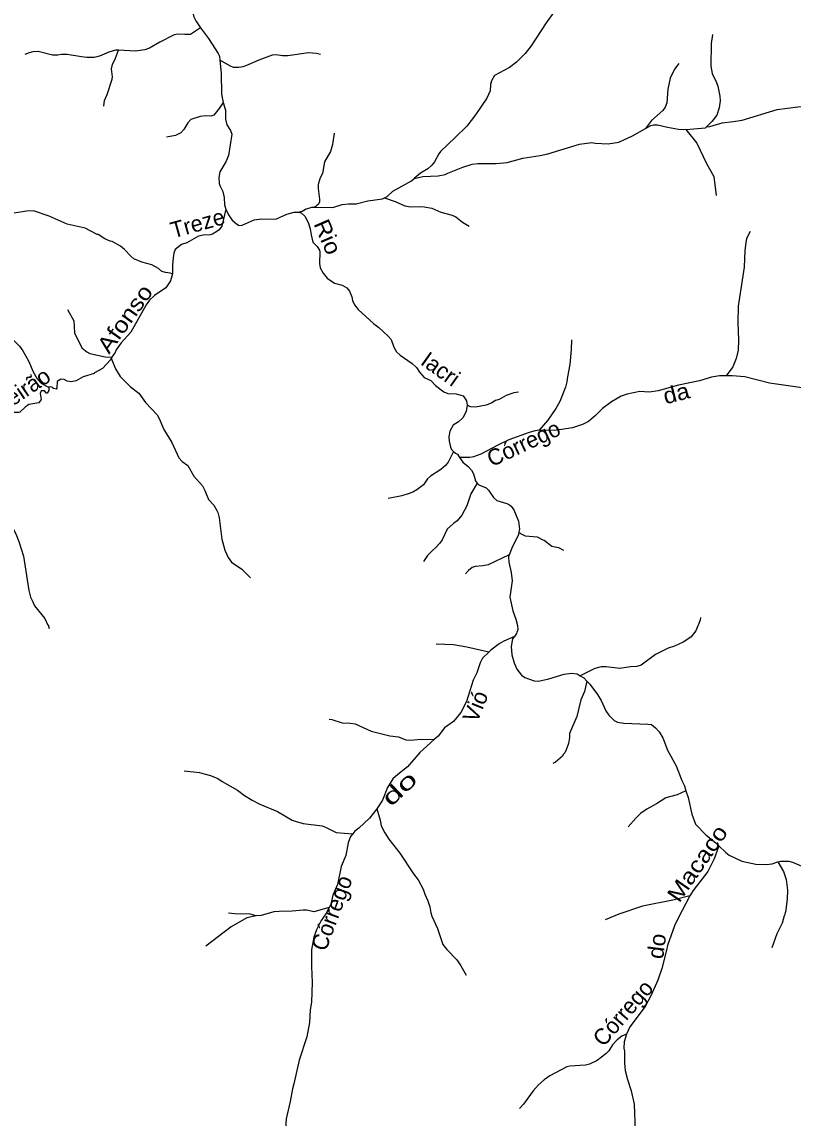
# Model space of a CAD drawing. Extents: x 551.6 to 577.6, y 7567 to 7594.7.
# Drawn here: x 558.55 to 563.33, y 7579.74 to 7586.53 of the extents above; entities that cross this region are included whole.
import ezdxf
from ezdxf.enums import TextEntityAlignment as Align

# ---------------------------------------------------------------- set-up
doc = ezdxf.new("R2010")
doc.units = 0
doc.header["$LTSCALE"] = 0.04
doc.layers.add('61', color=7, linetype='Continuous')
doc.layers.add('7', color=7, linetype='Continuous', lineweight=25)

msp = doc.modelspace()

# ---------------------------------------------------------------- linework, layer by layer
at = {"layer": '7'}
for points in [[(559.5927, 7586.7884), (559.5906, 7586.773), (559.6019, 7586.6313), (559.6188, 7586.5669), (559.6316, 7586.5412), (559.6598, 7586.4975)], [(562.1378, 7586.789), (562.0388, 7586.7271), (561.9632, 7586.6949), (561.9302, 7586.6739), (561.8505, 7586.5959), (561.8022, 7586.5291), (561.7104, 7586.3867), (561.6734, 7586.3392), (561.6195, 7586.2844), (561.5761, 7586.2522), (561.4835, 7586.2032), (561.4642, 7586.1694), (561.4585, 7586.1468), (561.4561, 7586.1066), (561.4352, 7586.0615), (561.3644, 7585.9585), (561.3104, 7585.8885), (561.2388, 7585.8184)], [(559.6598, 7586.4975), (559.5971, 7586.4575), (559.5633, 7586.4559), (559.5182, 7586.4591), (559.4964, 7586.4542), (559.4071, 7586.41), (559.3427, 7586.3722), (559.3138, 7586.3617), (559.2574, 7586.3544), (559.152, 7586.3605)], [(559.6598, 7586.4975), (559.7089, 7586.4317), (559.7701, 7586.3392), (559.7773, 7586.3231), (559.7798, 7586.2986)], [(562.834, 7586.4567), (562.8259, 7586.4011), (562.8243, 7586.2595), (562.8331, 7586.2144), (562.8597, 7586.1581), (562.8669, 7586.1356), (562.8806, 7586.0744), (562.8822, 7586.0454), (562.8758, 7586.002), (562.8613, 7585.9569), (562.8299, 7585.9166), (562.7969, 7585.8836)], [(559.152, 7586.3605), (559.1335, 7586.3601), (559.0908, 7586.348), (559.0337, 7586.3223), (558.9999, 7586.315), (558.9548, 7586.3142), (558.9226, 7586.3174), (558.8325, 7586.3335), (558.7971, 7586.3327), (558.7745, 7586.3279), (558.7424, 7586.3295), (558.6538, 7586.3504), (558.62, 7586.3496), (558.5975, 7586.344), (558.5709, 7586.3335)], [(559.0602, 7586.0124), (559.0651, 7586.047), (559.0803, 7586.084), (559.1117, 7586.179), (559.1134, 7586.1951), (559.1077, 7586.2434), (559.1142, 7586.2708), (559.1335, 7586.3094), (559.152, 7586.3605)], [(560.4043, 7586.3319), (560.3793, 7586.3392), (560.3294, 7586.3424), (560.2007, 7586.3247), (560.1685, 7586.3247), (560.1298, 7586.3303), (560.1041, 7586.3287), (560.0204, 7586.2981), (559.9455, 7586.2635), (559.9222, 7586.2563), (559.8964, 7586.253)], [(559.7798, 7586.2986), (559.7886, 7586.216), (559.7902, 7586.0857), (559.7993, 7586.0346)], [(559.8964, 7586.253), (559.8642, 7586.253), (559.8449, 7586.2603), (559.7798, 7586.2986)], [(562.6255, 7586.2764), (562.5989, 7586.2418), (562.5716, 7586.1855), (562.5571, 7586.1179), (562.5506, 7586.0325), (562.5402, 7586.0068), (562.5257, 7585.9851), (562.4557, 7585.9231), (562.4193, 7585.8736)], [(559.7993, 7586.0346), (559.7749, 7585.9971), (559.7419, 7585.9569), (559.7242, 7585.9504), (559.692, 7585.952), (559.6566, 7585.9472), (559.6003, 7585.9295), (559.5809, 7585.9094), (559.5568, 7585.8668), (559.5383, 7585.8474), (559.5053, 7585.8305), (559.4498, 7585.8201)], [(559.7993, 7586.0346), (559.8143, 7585.9875), (559.8143, 7585.9311), (559.824, 7585.8973), (559.8465, 7585.8619), (559.853, 7585.8378)], [(562.9627, 7585.9166), (563.0191, 7585.9263), (563.2347, 7585.9907), (563.3635, 7586.0084), (563.4504, 7586.0092), (563.5229, 7586.0003), (563.6162, 7585.9714), (563.7039, 7585.9335), (563.7321, 7585.9134), (563.7997, 7585.878), (563.8335, 7585.8563), (563.8842, 7585.8088)], [(562.1064, 7585.7838), (562.1869, 7585.779), (562.2529, 7585.7887), (562.339, 7585.8281), (562.4193, 7585.8736)], [(562.4193, 7585.8736), (562.4525, 7585.8925), (562.4686, 7585.8973), (562.4927, 7585.8965), (562.5555, 7585.8812), (562.6231, 7585.87), (562.6694, 7585.8681)], [(562.6694, 7585.8681), (562.7921, 7585.878), (562.7969, 7585.8836)], [(562.6694, 7585.8681), (562.7382, 7585.7831), (562.7985, 7585.6575), (562.8436, 7585.577), (562.8581, 7585.4587)], [(562.7969, 7585.8836), (562.8179, 7585.886), (562.8951, 7585.9086), (562.9627, 7585.9166)], [(559.853, 7585.8378), (559.8328, 7585.7058), (559.8159, 7585.6672), (559.7805, 7585.606), (559.7741, 7585.5706), (559.7757, 7585.5336), (559.7789, 7585.5207), (559.7982, 7585.4821), (559.8063, 7585.445), (559.8095, 7585.4), (559.8176, 7585.3735)], [(560.4896, 7585.845), (560.4775, 7585.775), (560.4662, 7585.7316), (560.4284, 7585.6672), (560.4163, 7585.5955), (560.401, 7585.5674), (560.3898, 7585.5271), (560.3898, 7585.5014), (560.3986, 7585.4354), (560.397, 7585.4161), (560.3889, 7585.4016), (560.3689, 7585.3865)], [(561.2388, 7585.8184), (561.1471, 7585.7307), (561.1366, 7585.7171), (561.1109, 7585.6672), (561.0948, 7585.6454), (561.069, 7585.6229), (561.0232, 7585.5971), (560.9854, 7585.5634)], [(561.1938, 7585.5963), (561.2871, 7585.6341), (561.3451, 7585.6527), (561.3789, 7585.6575), (561.4932, 7585.6559), (561.5608, 7585.6623), (561.659, 7585.6897), (561.7652, 7585.7058), (561.8135, 7585.717), (562.0098, 7585.7766), (562.0871, 7585.7863), (562.1064, 7585.7838)], [(560.9854, 7585.5634), (561.0376, 7585.5754), (561.1342, 7585.5802), (561.1761, 7585.5891), (561.1938, 7585.5963)], [(560.8011, 7585.444), (560.8163, 7585.4523), (560.8533, 7585.4845), (560.9682, 7585.5485), (560.9854, 7585.5634)], [(560.3689, 7585.3865), (560.4807, 7585.3839), (560.5387, 7585.4032), (560.5773, 7585.4072), (560.6256, 7585.4064), (560.698, 7585.4249), (560.7882, 7585.437), (560.8011, 7585.444)], [(560.8011, 7585.444), (560.8662, 7585.4209), (560.9266, 7585.3943), (560.962, 7585.3871), (561.0215, 7585.3903), (561.0457, 7585.3887), (561.094, 7585.379), (561.1503, 7585.3557), (561.2211, 7585.3364), (561.2421, 7585.3251), (561.2839, 7585.2929), (561.325, 7585.2672)], [(560.2681, 7585.3542), (560.29, 7585.3613), (560.3117, 7585.3742), (560.3503, 7585.3855), (560.3689, 7585.3865)], [(559.4867, 7584.9721), (559.4715, 7584.9774), (559.4425, 7584.9798), (559.42, 7584.9879), (559.3991, 7585.0048), (559.3572, 7585.0281), (559.2952, 7585.045), (559.2462, 7585.0652), (559.2276, 7585.0813), (559.189, 7585.1239), (559.1641, 7585.144), (559.111, 7585.173), (559.0997, 7585.1746), (559.0659, 7585.1891), (559.0256, 7585.2165), (559.0192, 7585.2165), (558.9436, 7585.2559), (558.8325, 7585.28), (558.7222, 7585.3291), (558.624, 7585.3629), (558.5798, 7585.3613), (558.5041, 7585.3484)], [(559.8176, 7585.3735), (559.7918, 7585.2688), (559.7749, 7585.2462), (559.7612, 7585.235), (559.7339, 7585.2189), (559.7194, 7585.2148), (559.6759, 7585.2132), (559.647, 7585.2052), (559.5745, 7585.1641), (559.5423, 7585.1537), (559.5021, 7585.1231), (559.494, 7585.1006), (559.4892, 7585.0716), (559.486, 7585.0265), (559.4867, 7584.9721)], [(559.8176, 7585.3735), (559.8328, 7585.3388), (559.8554, 7585.3058), (559.8819, 7585.2825), (559.8988, 7585.2728), (559.919, 7585.2744), (559.993, 7585.3074), (560.0381, 7585.3138), (560.1186, 7585.3106), (560.1314, 7585.313), (560.1958, 7585.3428), (560.2409, 7585.3549), (560.2681, 7585.3542)], [(560.2681, 7585.3542), (560.2843, 7585.3517), (560.3061, 7585.3292), (560.327, 7585.2905), (560.3407, 7585.2519), (560.3455, 7585.2133), (560.3568, 7585.1682)], [(563.0674, 7585.235), (563.0456, 7585.1907), (563.0408, 7585.165), (563.0351, 7585.1167), (563.0311, 7585.0137), (562.9941, 7584.7722), (562.9909, 7584.6692), (562.9957, 7584.563), (562.9941, 7584.4986), (562.982, 7584.4471), (562.9603, 7584.3956), (562.9199, 7584.3408)], [(560.3568, 7585.1682), (560.3825, 7585.1424), (560.397, 7585.1199), (560.4002, 7585.1086), (560.397, 7585.0362), (560.4018, 7585.0105), (560.4195, 7584.9766), (560.4445, 7584.9452), (560.4904, 7584.9147), (560.5387, 7584.9018), (560.5676, 7584.8849), (560.5837, 7584.864), (560.5982, 7584.8302), (560.6014, 7584.8076), (560.6143, 7584.7795), (560.6376, 7584.7521), (560.7318, 7584.6652), (560.7664, 7584.6402), (560.8243, 7584.5863), (560.8412, 7584.5646), (560.8582, 7584.5179), (560.8759, 7584.4889), (560.8976, 7584.4672), (560.9732, 7584.4157), (560.999, 7584.3908), (561.0175, 7584.3634)], [(559.4867, 7584.9721), (559.4739, 7584.93), (559.4441, 7584.8857), (559.3749, 7584.8382), (559.3427, 7584.8093), (559.3234, 7584.7803), (559.2268, 7584.6113), (559.1673, 7584.5437), (559.1367, 7584.5002), (559.1254, 7584.4753), (559.1222, 7584.4745), (559.1102, 7584.4558), (559.1061, 7584.4495)], [(558.8341, 7584.7521), (558.8743, 7584.6805), (558.8784, 7584.6064), (558.9242, 7584.5139), (558.954, 7584.4881), (558.9725, 7584.4793), (559.0675, 7584.4567), (559.1102, 7584.4558)], [(558.3343, 7584.6724), (558.3738, 7584.6563), (558.4349, 7584.6201), (558.4856, 7584.5759), (558.5363, 7584.5243), (558.5588, 7584.4954), (558.5943, 7584.4278), (558.6192, 7584.3698), (558.6474, 7584.3215), (558.6723, 7584.2942), (558.7037, 7584.2748), (558.7194, 7584.2696)], [(561.9599, 7584.5638), (561.9583, 7584.5034), (561.9495, 7584.4101), (561.935, 7584.3344), (561.9318, 7584.3022), (561.9229, 7584.27), (561.8883, 7584.1815), (561.8634, 7584.138), (561.8126, 7584.0648), (561.7608, 7584.0026)], [(559.1061, 7584.4495), (559.1021, 7584.4382), (559.053, 7584.3859), (559.0031, 7584.3577), (559.0007, 7584.3537), (558.9323, 7584.3336), (558.8888, 7584.3086), (558.8582, 7584.303)], [(559.1061, 7584.4495), (559.1335, 7584.3827), (559.1624, 7584.336), (559.2252, 7584.2708), (559.2783, 7584.233), (559.3194, 7584.1751), (559.391, 7584.0978), (559.4039, 7584.0753), (559.4329, 7584.0077), (559.4811, 7583.9272), (559.5262, 7583.8306), (559.5463, 7583.8081), (559.5809, 7583.7839), (559.618, 7583.7179), (559.6711, 7583.6584), (559.6872, 7583.6294), (559.7097, 7583.5723), (559.7419, 7583.5377), (559.762, 7583.5039), (559.7677, 7583.4926), (559.7757, 7583.4588)], [(561.0175, 7584.3634), (561.0457, 7584.3304), (561.0875, 7584.3119), (561.1173, 7584.2805), (561.168, 7584.241), (561.1938, 7584.2306), (561.2453, 7584.229), (561.2895, 7584.2153), (561.3096, 7584.1847), (561.3136, 7584.1572)], [(558.8582, 7584.303), (558.8325, 7584.3078), (558.8148, 7584.3175), (558.7939, 7584.3191), (558.7761, 7584.3095), (558.7713, 7584.3038), (558.7689, 7584.2636), (558.7641, 7584.2563), (558.7456, 7584.262), (558.7456, 7584.2652), (558.7388, 7584.2703), (558.7269, 7584.2725), (558.7194, 7584.2696)], [(562.9199, 7584.3408), (562.879, 7584.3408), (562.8275, 7584.3312), (562.7535, 7584.3086), (562.6247, 7584.2813), (562.4976, 7584.2459), (562.4412, 7584.2378), (562.3833, 7584.2427), (562.306, 7584.2257), (562.2674, 7584.2129), (562.2078, 7584.1783), (562.1523, 7584.1364), (562.1096, 7584.093), (562.0662, 7584.0575), (562.0292, 7584.039), (561.9664, 7584.0173), (561.8988, 7584.006), (561.8537, 7584.0012), (561.7608, 7584.0026)], [(563.7353, 7584.2636), (563.6951, 7584.2604), (563.6307, 7584.2378), (563.605, 7584.2362), (563.5019, 7584.2507), (563.4553, 7584.2604), (563.3909, 7584.266), (563.1881, 7584.295), (563.0352, 7584.3336), (562.9563, 7584.3408), (562.9199, 7584.3408)], [(558.7194, 7584.2696), (558.7182, 7584.2491), (558.7094, 7584.2314), (558.7037, 7584.2322), (558.6925, 7584.2467), (558.6707, 7584.2475), (558.6651, 7584.2298), (558.6723, 7584.1928), (558.6578, 7584.1734), (558.5951, 7584.1614), (558.5725, 7584.1453), (558.5395, 7584.1139), (558.5331, 7584.1115), (558.4961, 7584.1123), (558.4575, 7584.1026), (558.4349, 7584.0857), (558.3955, 7584.0398), (558.3593, 7584.0052), (558.3142, 7583.9754), (558.2723, 7583.9567), (558.204, 7583.9281), (558.1211, 7583.8998)], [(561.6308, 7584.2395), (561.6026, 7584.2338), (561.5543, 7584.2177), (561.5109, 7584.1936), (561.4883, 7584.1863), (561.4666, 7584.1726), (561.4304, 7584.1573), (561.366, 7584.1453), (561.3338, 7584.1485), (561.3136, 7584.1572)], [(561.3136, 7584.1572), (561.3064, 7584.1187), (561.2855, 7584.0793), (561.2598, 7584.0543), (561.2267, 7584.0342), (561.2066, 7583.9964), (561.2002, 7583.961), (561.201, 7583.9352), (561.209, 7583.8966), (561.2163, 7583.8837), (561.2294, 7583.8706)], [(561.7608, 7584.0026), (561.7346, 7583.9996), (561.6976, 7583.9891), (561.572, 7583.9425), (561.5076, 7583.9127), (561.3982, 7583.8547), (561.3531, 7583.837), (561.3306, 7583.8338), (561.2667, 7583.8339)], [(558.204, 7583.9281), (558.2128, 7583.8692), (558.224, 7583.8403), (558.319, 7583.6793), (558.3681, 7583.5731), (558.3858, 7583.5449), (558.4631, 7583.4572), (558.5138, 7583.3606), (558.5331, 7583.3123), (558.5613, 7583.2206), (558.5943, 7583.0081), (558.6063, 7582.9663), (558.6192, 7582.9373)], [(561.2294, 7583.8706), (561.1946, 7583.8048), (561.1785, 7583.7847), (561.1503, 7583.7598), (561.0851, 7583.7179), (561.0682, 7583.7018), (561.0417, 7583.6648), (561.0022, 7583.6326), (560.9765, 7583.6181), (560.9475, 7583.6077), (560.9089, 7583.5964), (560.8228, 7583.5795)], [(561.2294, 7583.8706), (561.2404, 7583.8596), (561.2525, 7583.8547), (561.2667, 7583.8339)], [(561.2667, 7583.8339), (561.2871, 7583.804), (561.3193, 7583.7775), (561.341, 7583.755), (561.3531, 7583.7324), (561.3628, 7583.697)], [(561.3628, 7583.697), (561.3628, 7583.6898), (561.3754, 7583.6749)], [(561.3754, 7583.6749), (561.3362, 7583.6085), (561.3113, 7583.5344), (561.2807, 7583.4749), (561.2517, 7583.4403), (561.2284, 7583.4242), (561.1897, 7583.388), (561.1583, 7583.3236), (561.1447, 7583.3027), (561.1197, 7583.2745), (561.0996, 7583.2592), (561.0666, 7583.2254), (561.0417, 7583.1876)], [(561.3754, 7583.6749), (561.3853, 7583.6632), (561.4304, 7583.6455), (561.4457, 7583.631), (561.4762, 7583.5851), (561.498, 7583.5666), (561.5591, 7583.5481), (561.5768, 7583.5393), (561.5857, 7583.5312), (561.6018, 7583.5087), (561.6324, 7583.4395), (561.6372, 7583.3896), (561.6343, 7583.372)], [(559.7757, 7583.4588), (559.7918, 7583.3268), (559.8111, 7583.2592), (559.832, 7583.2141), (559.8514, 7583.1852), (559.9158, 7583.1401), (559.9705, 7583.0862)], [(561.6343, 7583.372), (561.6315, 7583.355), (561.5897, 7583.2721), (561.5747, 7583.2296)], [(561.6343, 7583.372), (561.6445, 7583.3622), (561.6726, 7583.3477), (561.7483, 7583.3413), (561.7829, 7583.322), (561.7909, 7583.3212), (561.8384, 7583.2825), (561.8795, 7583.2745), (561.9108, 7583.2584)], [(561.5747, 7583.2296), (561.4432, 7583.1682), (561.4111, 7583.161), (561.3628, 7583.157), (561.3451, 7583.1505), (561.3209, 7583.132), (561.3024, 7583.1119)], [(561.5747, 7583.2296), (561.5704, 7583.2174), (561.5712, 7583.1836), (561.5865, 7583.1192), (561.5929, 7583.0677), (561.5785, 7582.9663), (561.5962, 7582.8826), (561.6155, 7582.8311), (561.6259, 7582.7924), (561.6267, 7582.7667), (561.6235, 7582.7522), (561.6203, 7582.7506)], [(558.6192, 7582.9373), (558.6313, 7582.9139), (558.6941, 7582.8343), (558.7134, 7582.794), (558.715, 7582.7956), (558.7214, 7582.7739)], [(562.7599, 7582.8415), (562.7583, 7582.8246), (562.7317, 7582.7578), (562.7004, 7582.7192), (562.6537, 7582.6878), (562.599, 7582.6636), (562.5603, 7582.6516), (562.4806, 7582.6113), (562.3929, 7582.5453), (562.3656, 7582.5373), (562.3269, 7582.5349), (562.2593, 7582.5244), (562.1756, 7582.5349), (562.1434, 7582.5341), (562.1048, 7582.5252), (562.0149, 7582.4798)], [(561.6203, 7582.7506), (561.6187, 7582.7425), (561.6076, 7582.7239)], [(561.4468, 7582.6267), (561.3113, 7582.658), (561.2276, 7582.6709), (561.1221, 7582.6749)], [(561.6076, 7582.7239), (561.5398, 7582.6942), (561.5109, 7582.6773), (561.4594, 7582.6395), (561.4468, 7582.6267)], [(561.6076, 7582.7239), (561.5953, 7582.7095), (561.5865, 7582.6604), (561.5897, 7582.6105), (561.6042, 7582.559), (561.6219, 7582.5204), (561.6493, 7582.4826), (561.6702, 7582.4697), (561.7298, 7582.4487), (561.7555, 7582.4471), (561.8199, 7582.46), (561.9149, 7582.4906), (561.9599, 7582.4954), (561.9953, 7582.4914), (562.0149, 7582.4798)], [(561.4468, 7582.6267), (561.4086, 7582.588), (561.3933, 7582.559), (561.3724, 7582.4979), (561.3515, 7582.4528), (561.3088, 7582.3208), (561.2734, 7582.2524), (561.2276, 7582.1968), (561.1728, 7582.1574), (561.1326, 7582.1051), (561.1095, 7582.0842)], [(562.0149, 7582.4798), (562.0372, 7582.4665), (562.0564, 7582.4465)], [(562.0564, 7582.4465), (562.0404, 7582.382), (562.0179, 7582.3305), (561.9937, 7582.2275), (561.947, 7582.1212), (561.947, 7582.0971), (561.9414, 7582.0601), (561.9277, 7582.0214), (561.9181, 7582.0013), (561.9084, 7581.9916), (561.9036, 7581.9812), (561.8602, 7581.9441), (561.8449, 7581.9361)], [(562.0564, 7582.4465), (562.075, 7582.427), (562.1209, 7582.3643), (562.1434, 7582.3256), (562.174, 7582.2613), (562.1925, 7582.2347), (562.2239, 7582.2033), (562.2465, 7582.1912), (562.2851, 7582.1848), (562.4332, 7582.1799)], [(560.4574, 7582.2097), (560.4743, 7582.2081), (560.5387, 7582.1872), (560.587, 7582.1856), (560.6191, 7582.1808), (560.7173, 7582.1357), (560.8348, 7582.1067), (560.8871, 7582.1019), (560.933, 7582.0818), (560.9572, 7582.0794), (561.0296, 7582.0874), (561.1095, 7582.0842)], [(562.4332, 7582.1799), (562.4557, 7582.1767), (562.4822, 7582.1558), (562.504, 7582.1325), (562.5265, 7582.0955), (562.5547, 7582.0182), (562.6086, 7581.9216), (562.644, 7581.8299), (562.6601, 7581.7977), (562.6703, 7581.7659)], [(561.1095, 7582.0842), (561.0207, 7582.0037), (560.9443, 7581.9152), (560.8831, 7581.8669)], [(559.5576, 7581.891), (559.6534, 7581.879), (559.6824, 7581.8725), (559.721, 7581.8613), (559.7677, 7581.8419), (559.7934, 7581.8242), (559.89, 7581.7703), (559.9318, 7581.7365), (559.9801, 7581.7091), (560.0284, 7581.6834), (560.1379, 7581.6375), (560.228, 7581.5852), (560.2473, 7581.5772), (560.2956, 7581.5643), (560.4147, 7581.5498), (560.434, 7581.5417)], [(560.8831, 7581.8669), (560.8525, 7581.8395), (560.8195, 7581.7864), (560.7881, 7581.7092), (560.7531, 7581.6539)], [(562.6703, 7581.7659), (562.6151, 7581.7413), (562.5458, 7581.7236), (562.4879, 7581.6858), (562.4283, 7581.652), (562.3889, 7581.6263), (562.3583, 7581.5965), (562.3124, 7581.5426)], [(562.6703, 7581.7659), (562.6834, 7581.7253), (562.7068, 7581.6206), (562.7285, 7581.5603), (562.7945, 7581.4902), (562.8549, 7581.4436), (562.8741, 7581.4251)], [(560.7531, 7581.6539), (560.7069, 7581.5973), (560.6409, 7581.5337), (560.6159, 7581.5152), (560.6041, 7581.5)], [(560.7531, 7581.6539), (560.7737, 7581.5852), (560.7801, 7581.549), (560.8018, 7581.5064), (560.8276, 7581.4661), (560.8968, 7581.3792), (560.9797, 7581.252), (561.0103, 7581.215), (561.0408, 7581.1571), (561.0505, 7581.1249), (561.0698, 7581.0846), (561.0827, 7581.0476), (561.0875, 7581.009), (561.0932, 7580.9897), (561.1294, 7580.9124), (561.1632, 7580.8126), (561.1873, 7580.7828)], [(560.434, 7581.5417), (560.5016, 7581.5071), (560.6041, 7581.5)], [(560.6041, 7581.5), (560.5902, 7581.4822), (560.5757, 7581.4436), (560.5612, 7581.3647), (560.5322, 7581.2971), (560.5097, 7581.186), (560.4807, 7581.12), (560.4686, 7581.0637), (560.4573, 7581.0419)], [(562.8741, 7581.4251), (562.8452, 7581.3438), (562.8058, 7581.2665), (562.7156, 7581.1474), (562.695, 7581.1144)], [(562.8741, 7581.4251), (562.9176, 7581.3832), (562.9386, 7581.3671), (563.0175, 7581.3309), (563.1028, 7581.3116), (563.1671, 7581.3092), (563.2042, 7581.314), (563.24, 7581.325)], [(563.24, 7581.325), (563.275, 7581.2649), (563.2911, 7581.2166), (563.2991, 7581.1506), (563.2983, 7581.0943), (563.2878, 7581.013), (563.2846, 7581.0106), (563.2814, 7580.9929), (563.2782, 7580.9913), (563.2677, 7580.9462), (563.2331, 7580.8786), (563.2026, 7580.7925)], [(563.24, 7581.325), (563.2565, 7581.3301), (563.3072, 7581.3301), (563.3313, 7581.3244), (563.3877, 7581.2995), (563.4263, 7581.2762), (563.4673, 7581.2416), (563.5019, 7581.2029), (563.5191, 7581.1888)], [(562.695, 7581.1144), (562.5893, 7581.0886), (562.401, 7581.05), (562.2545, 7581.0009), (562.1684, 7580.9655)], [(562.695, 7581.1144), (562.6215, 7580.9768), (562.5989, 7580.9285), (562.5547, 7580.8078), (562.5498, 7580.7788), (562.5201, 7580.6645), (562.4951, 7580.5921), (562.4533, 7580.4939)], [(560.4573, 7581.0419), (560.3632, 7581.0154), (560.3182, 7581.0251), (560.2956, 7581.0267), (560.228, 7581.0202), (560.1475, 7581.0186), (560.1137, 7581.0154), (560.0349, 7580.9929), (560.0043, 7580.9912)], [(560.4573, 7581.0419), (560.4372, 7581.0033), (560.4075, 7580.9623), (560.3793, 7580.9044)], [(560.0043, 7580.9912), (559.9479, 7580.9784), (559.849, 7580.9229), (559.6928, 7580.8021)], [(560.0043, 7580.9912), (559.9673, 7581.0017), (559.8723, 7581.0033), (559.8329, 7581.0074)], [(560.3793, 7580.9044), (560.3632, 7580.8593), (560.3487, 7580.7804), (560.3471, 7580.6774), (560.3519, 7580.5776), (560.3471, 7580.4553), (560.3407, 7580.407), (560.3358, 7580.3297), (560.3181, 7580.2396), (560.2715, 7580.0963), (560.2393, 7579.9499), (560.2296, 7579.9177), (560.2151, 7579.8404)], [(561.1873, 7580.7828), (561.2493, 7580.7176), (561.275, 7580.6814), (561.3081, 7580.6219)], [(562.4533, 7580.4939), (562.4162, 7580.4295), (562.3229, 7580.3024), (562.302, 7580.2565)], [(562.302, 7580.2565), (562.2722, 7580.2452), (562.244, 7580.2219), (562.215, 7580.1913), (562.1917, 7580.1535), (562.1732, 7580.1341), (562.1185, 7580.0947), (562.0726, 7580.0706), (562.0469, 7580.0657), (561.9503, 7580.0593), (561.9318, 7580.0545), (561.8255, 7579.9981), (561.7909, 7579.974), (561.7563, 7579.9418)], [(562.302, 7580.2565), (562.2867, 7580.209), (562.2851, 7580.1704), (562.2883, 7580.1511), (562.2883, 7580.077), (562.2931, 7580.032), (562.3068, 7579.9756), (562.3301, 7579.9048), (562.3494, 7579.8227), (562.3543, 7579.6585), (562.368, 7579.6102), (562.372, 7579.57), (562.3736, 7579.3913), (562.3784, 7579.3503)], [(561.7563, 7579.9418), (561.7217, 7579.9056), (561.6622, 7579.8227), (561.6388, 7579.7961)], [(560.2151, 7579.8404), (560.191, 7579.731), (560.1861, 7579.6698), (560.1789, 7579.6247), (560.1556, 7579.5346), (560.1347, 7579.5032), (560.1153, 7579.4871), (560.0944, 7579.475), (560.0711, 7579.4461), (560.0228, 7579.3366), (560.0011, 7579.265)]]:
    msp.add_lwpolyline(points, dxfattribs=at)

# ---------------------------------------------------------------- texts
at = {"layer": '61'}
for s, rotation, p in [('Treze', 15.565, (559.6549, 7585.2377)), ('Iacri', 324.55, (561.12, 7584.3417)), ('Ribeirão', 33.919, (558.534, 7584.1751)), ('Córrego', 25.146, (561.6843, 7583.8755)), ('Vió', 67.888, (561.4107, 7582.2713)), ('Córrego', 69.577, (560.5204, 7580.9913)), ('Córrego', 49.068, (562.3172, 7580.3556))]:
    msp.add_text(s, height=0.1, rotation=rotation, dxfattribs=at).set_placement(p, align=Align.CENTER)
for s, rotation, width, p in [('Rio', 293.365, 1.1, (560.4028, 7585.1818)), ('Afonso', 54.568, 1.15, (559.2316, 7584.6652)), ('da', 14.569, 1.1, (562.6224, 7584.1831)), ('do', 43.113, 1.6, (560.927, 7581.7443)), ('Macaco', 55.284, 1.15, (562.7818, 7581.2877)), ('do', 82.596, 1.05, (562.5381, 7580.7968))]:
    msp.add_text(s, height=0.1, rotation=rotation, dxfattribs=dict(at, width=width)).set_placement(p, align=Align.CENTER)

doc.saveas('drawing.dxf')
